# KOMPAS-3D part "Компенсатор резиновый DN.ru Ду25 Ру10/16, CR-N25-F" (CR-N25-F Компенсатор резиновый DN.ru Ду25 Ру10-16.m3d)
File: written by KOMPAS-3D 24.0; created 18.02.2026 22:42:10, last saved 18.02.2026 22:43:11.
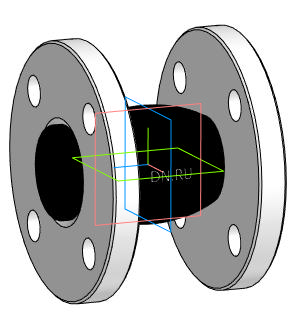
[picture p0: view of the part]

Document properties: Автор: DN.RU; Полное имя файла: D:\PROJECT CAD\DN.RU\...178(1)(ACTUALE). CR-N25-F Компенсатор резиновый DN.ru Ру10-16\DN25\CR-N25-F Компенсатор резиновый DN.ru Ду25 Ру10-16.m3d

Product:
- Body: Твердое тело2  | qty 1
    Масса: 2.501783
- Part/product: Компенсатор резиновый DN.ru Ду25 Ру10/16  | designation CR-N25-F
    Масса: 2
    Раздел спецификации: Прочие изделия
    Комментарий: D140-02388
    Примечание: D140-02388
    additional columns: Типовые

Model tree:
1. Твердое тело2  (labels: Твердое тело2)

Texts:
  CR-N25-F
